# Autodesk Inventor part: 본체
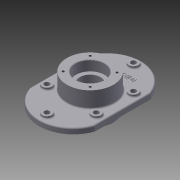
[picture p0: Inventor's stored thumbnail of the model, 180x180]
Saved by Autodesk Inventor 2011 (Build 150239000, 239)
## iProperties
Created: 2015-02
Part Number: 본체
Material: 알루미늄-6061
Document SubType Name: Modeling
Designer: Administrator
Mass: 1637.12 g
Surface Area: 925.885 cm^2
Volume: 604.103 cm^3
Density: 2.71 g/cm^3
Author: Administrator
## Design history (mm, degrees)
sketch "스케치1"
  geometry: L1 (70, 60)-(70, -60); L2 (-70, -60)-(-70, 60); L3 (-53, -87.643)-(-53, -87.818); C1 r 50 at (0, 0); A1 r 74 centre (0, 36) between (70, 60) and (-70, 60); A2 r 74 centre (0, -36) between (-70, -60) and (70, -60); 3 further points
  constraints: 6 end point, 6 point on circle, 3 centre point, 1 coincident, 1 horizontal alignment, 1 parallel, 1 vertical alignment
  dimensions: "d2" = 100 diameter of C1
extrude "돌출1" new body sketch "스케치1" distance "d6" = 12; taper "d7" = 0 deg
extrude "돌출2" join sketch "스케치1" distance "d8" = 47; taper "d10" = 0 deg; dims "d9" = 23, "d11" = 0
sketch "스케치2"
  geometry: L1 (70, 60)-(70, -60) reference; L2 (-70, -60)-(-70, 60) reference; L3 (-53, 60)-(-53, -60); L4 (53, -60)-(53, 60); C1 r 10 at (0, 93); C2 r 10 at (0, -93); C3 r 10 at (-53, 40); C4 r 10 at (53, 40); C5 r 10 at (53, -40); C6 r 10 at (-53, -40); A1 r 59.06 centre (0, -33.94) between (-53, -60) and (53, -60) reference; A2 r 59.061 centre (0, 33.939) between (53, 60) and (-53, 60) reference
  constraints: 8 centre point, 6 point on circle, 5 equal radius, 4 end point, 4 point on line, 2 parallel, 2 other
  dimensions: "d12" = 17 distance between parallel lines of L1 L4; "d13" = 17 distance between parallel lines of L2 L3; "d16" = 20 diameter of C1
extrude "돌출3" join sketch "스케치2" distance "d20" = 5; taper "d21" = 0 deg
sketch "스케치3"
  geometry: C1 r 10 at (0, 0) reference; C2 r 10 at (-53, 53) reference; C3 r 10 at (-53, 133) reference; C4 r 10 at (0, 186) reference; C5 r 10 at (53, 133) reference; C6 r 10 at (53, 53) reference; 7 further points
  constraints: 6 coincident
hole "Hole1" sketch "스케치3" at (0, 0), (-53, 53), (-53, 133), (0, 186), (53, 133), (53, 53) diameter "d22" = 11; stored, may be unused: countersink angle "d26" = 90 deg, drill point angle "d28" = 118 deg; dims "d23" = 6, "d24" = 4, "d25" = 2, "d27" = 8
sketch "스케치4"
  geometry: C1 r 50 at (0, 0) reference; 1 further point
  constraints: 1 coincident
hole "Hole2" sketch "스케치4" at (0, 0) diameter "d29" = 45; stored, may be unused: countersink angle "d33" = 90 deg, drill point angle "d35" = 0 deg; dims "d30" = 6, "d31" = 62, "d32" = 22, "d34" = 48
sketch "스케치5"
  geometry: C1 r 50 at (0, 0) reference; 1 further point
  constraints: 1 coincident
hole "Hole3" sketch "스케치5" at (0, 0) diameter "d36" = 45; stored, may be unused: countersink angle "d40" = 90 deg, drill point angle "d42" = 0 deg; dims "d37" = 6, "d38" = 62, "d39" = 22, "d41" = 48
sketch "스케치6" dims "d43" = 82
  geometry: L1 (0, 46.296)-(0, -46.961); L2 (-40.999, -0.333)-(-34.714, -0.333); L3 (-34.714, -0.333)-(40.999, -0.333); L4 (-28.991, 28.991)-(0, 0); L5 (28.991, 28.991)-(0, 0); L6 (0, 0)-(28.991, -28.991); L7 (-28.991, -28.991)-(0, 0); C1 r 50 at (0, 0) reference; 1 further point
  constraints: 14 end point, 2 perpendicular, 1 coincident, 1 collinear, 1 vertical, 9 other
  dimensions: "d44" = 45 deg angle of L3 L5; "d45" = 45 deg angle of L1 L4
hole "Hole4" sketch "스케치6" at (-28.991, 28.991), (31, 26.833), (-28.991, -28.991), (28.991, -28.991) diameter "d46" = 4.917; stored, may be unused: countersink angle "d50" = 90 deg, drill point angle "d52" = 118 deg; dims "d47" = 10, "d48" = 62, "d49" = 22, "d51" = 13
sketch "스케치7" dims "d53" = 82
  geometry: L1 (0, 41)-(0, -41); L2 (-41, 0)-(-34.124, 0); L3 (-34.124, 0)-(41, 0); L4 (28.991, -28.991)-(0, 0); L5 (-28.991, 28.991)-(0, 0); L6 (-28.991, -28.991)-(0, 0); L7 (0, 0)-(28.991, 28.991); C1 r 50 at (0, 0) reference
  constraints: 14 end point, 2 collinear, 1 coincident, 1 perpendicular, 1 vertical, 10 other
  dimensions: "d55" = 45 deg angle of L3 L7; "d56" = 45 deg angle of L1 L6
hole "Hole5" sketch "스케치7" at (-28.991, 28.991), (28.991, 28.991), (28.991, -28.991), (-28.991, -28.991) diameter "d57" = 4.917; stored, may be unused: countersink angle "d61" = 90 deg, drill point angle "d63" = 118 deg; dims "d58" = 10, "d59" = 62, "d60" = 22, "d62" = 13
fillet "모깎기1" dims "d64" = 0.3
fillet "모깎기2" dims "d65" = 3
chamfer "모따기1" distance "d66" = 1; stored, may be unused: second distance "d67" = 2, angle "d68" = 45 deg
sketch "스케치8"
  geometry: C1 r 53 at (0, 0) reference; C2 r 13 at (0, 93) reference; 1 further point
  constraints: 1 vertical alignment, 1 other
  dimensions: "d69" = 65 distance of C1.centre point (0, 65)
extrude "돌출4" join sketch "스케치8" distance "d70" = 1; taper "d71" = 0 deg
node "솔리드1"
node "투영된 루프1"
node "투영된 루프2"
node "투영된 루프3"
node "투영된 루프4"
node "투영된 루프5"
other parameters: "d3" = 17
